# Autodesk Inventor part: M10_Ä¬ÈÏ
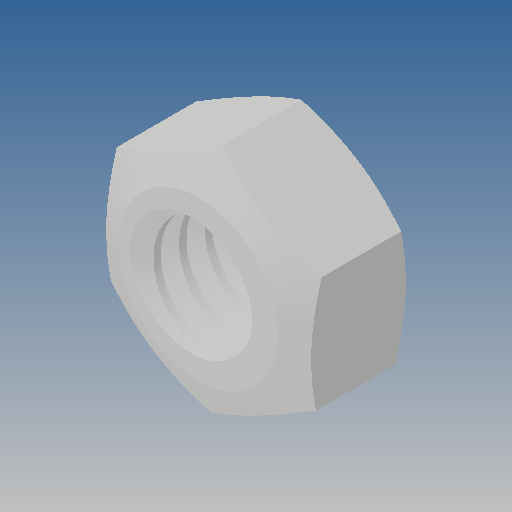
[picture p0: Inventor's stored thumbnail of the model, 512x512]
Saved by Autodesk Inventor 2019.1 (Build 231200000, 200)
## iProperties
Created: 2010-06
Part Number: M10_Ä¬ÈÏ
Material: Ogólny
Document SubType Name: Modeling
Designer: CADENGINEERING4
Density: 1 g/cm^3
Appearance: Domyślna
Author: CADENGINEERING4
Revision Number: ÈÎºÎ
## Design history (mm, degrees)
feature "NONE"
node "Bryła1"
